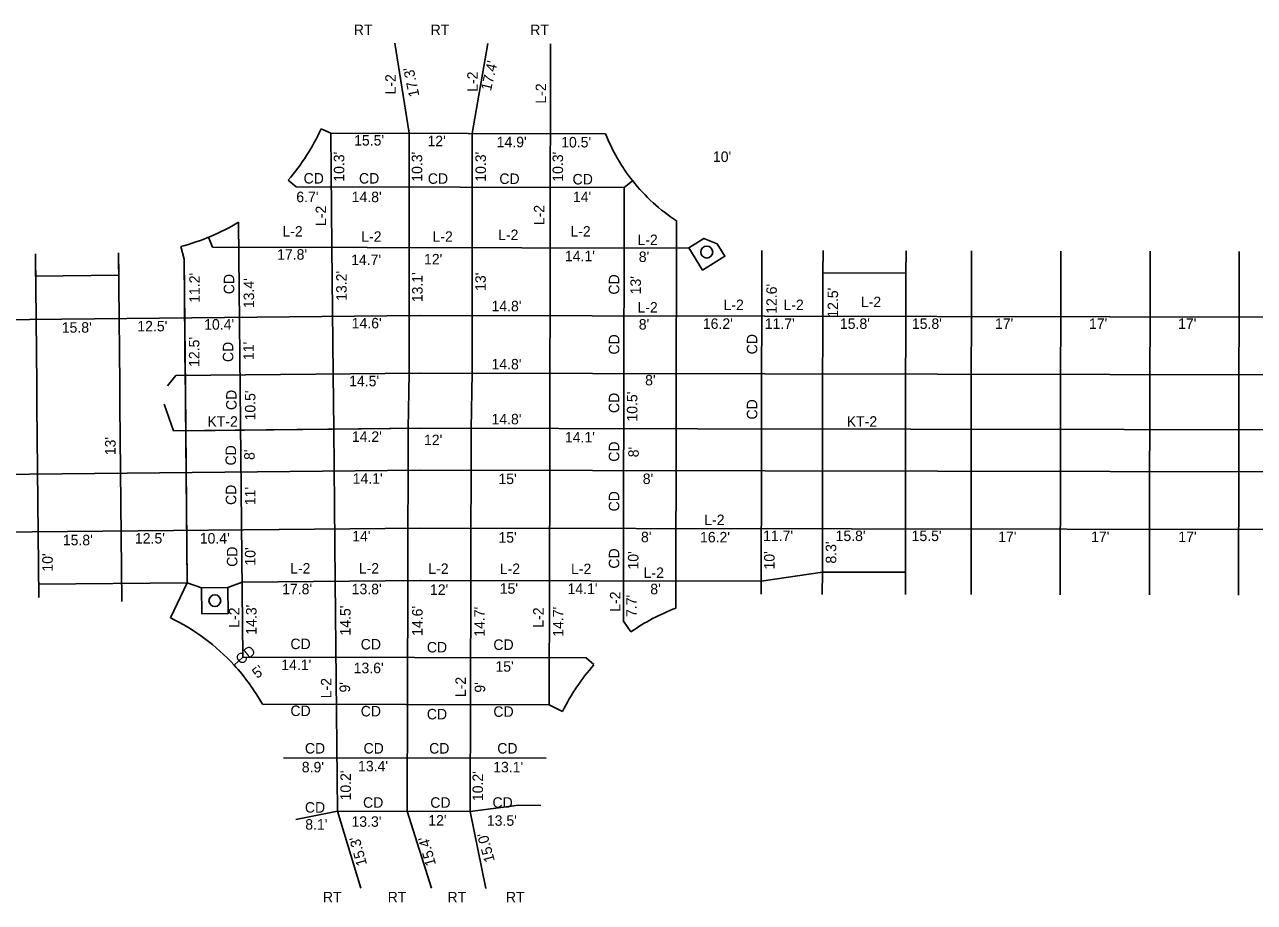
# Model space of a CAD drawing. Extents: x 4995357 to 4999033, y 3881202 to 3881750.
# Drawn here: x 4995617.7 to 4995852.2, y 3881583 to 3881750.3 of the extents above; entities that cross this region are included whole.
import ezdxf

# ---------------------------------------------------------------- set-up
doc = ezdxf.new("R2010")
doc.units = 0
for name, color, linetype in [('dsn3DCenterLine', 7, 'Continuous'), ('dsn3DCurbFormgrade', 7, 'Continuous'), ('dsn3DCurbTop', 7, 'Continuous'), ('dsn3DDitchFront', 7, 'Continuous'), ('dsn3DDNC', 7, 'Continuous'), ('dsn3DExistingPvmtBtm', 7, 'Continuous'), ('dsn3DGroundLineIntercept', 7, 'Continuous'), ('dsn3DIntakeWell', 7, 'Continuous')]:
    doc.layers.add(name, color=color, linetype=linetype)

msp = doc.modelspace()

# ---------------------------------------------------------------- linework, layer by layer
at = {"layer": 'dsn3DCurbFormgrade'}
for p, q in [((4995731.95, 3881673.26), (4995732.03, 3881719.19)), ((4995652.8, 3881709.73), (4995653.56, 3881707.88)), ((4995620.03, 3881681.6), (4995619.78, 3881706.6)), ((4995635.87, 3881681.76), (4995635.62, 3881706.76)), ((4995647.52, 3881708), (4995648.13, 3881705.57)), ((4995676.55, 3881683.66), (4995676.31, 3881707.83)), ((4995691.04, 3881683.81), (4995691.03, 3881707.8)), ((4995703.04, 3881683.81), (4995703.03, 3881707.77)), ((4995717.85, 3881673.28), (4995717.91, 3881707.74)), ((4995758.19, 3881670.71), (4995758.26, 3881707.21)), ((4995769.93, 3881707.19), (4995769.92, 3881702.94)), ((4995798.26, 3881707.14), (4995798.2, 3881670.64)), ((4995815.26, 3881707.11), (4995815.2, 3881670.61)), ((4995832.26, 3881707.07), (4995832.2, 3881670.57)), ((4995849.26, 3881707.04), (4995849.2, 3881670.54)), ((4995648.36, 3881681.88), (4995648.13, 3881705.57)), ((4995648.38, 3881680.71), (4995648.13, 3881705.57)), ((4995769.86, 3881670.69), (4995769.92, 3881702.94)), ((4995785.68, 3881670.66), (4995785.74, 3881702.91)), ((4995676.65, 3881673.17), (4995676.55, 3881683.66)), ((4995690.85, 3881673.31), (4995691.04, 3881683.81)), ((4995702.85, 3881673.31), (4995703.04, 3881683.81)), ((4995648.74, 3881643.89), (4995648.38, 3881680.71)), ((4995620.44, 3881641.1), (4995620.07, 3881677.6)), ((4995636.28, 3881640.35), (4995635.91, 3881677.76)), ((4995648.74, 3881643.89), (4995648.4, 3881677.88)), ((4995690.85, 3881673.31), (4995690.77, 3881644.3)), ((4995702.85, 3881673.31), (4995702.77, 3881644.31)), ((4995717.82, 3881665.28), (4995717.85, 3881673.28)), ((4995731.95, 3881673.26), (4995731.92, 3881665.26)), ((4995676.94, 3881644.17), (4995676.65, 3881673.17)), ((4995758.18, 3881667.72), (4995758.13, 3881641.71)), ((4995769.84, 3881667.7), (4995769.8, 3881645.94)), ((4995785.66, 3881667.67), (4995785.62, 3881645.91)), ((4995798.19, 3881667.64), (4995798.14, 3881641.64)), ((4995815.19, 3881667.61), (4995815.14, 3881641.61)), ((4995832.19, 3881667.57), (4995832.14, 3881641.57)), ((4995849.19, 3881667.54), (4995849.14, 3881641.54)), ((4995717.82, 3881665.28), (4995717.78, 3881644.28)), ((4995731.92, 3881665.26), (4995731.88, 3881644.26)), ((4995645.53, 3881637.22), (4995648.74, 3881643.89)), ((4995659.33, 3881629.72), (4995724.77, 3881629.61)), ((4995663.06, 3881620.74), (4995717.74, 3881620.65)), ((4995702.66, 3881600.33), (4995711.91, 3881601.49)), ((4995711.91, 3881601.49), (4995716.16, 3881601.47)), ((4995669.44, 3881598.79), (4995677.38, 3881600.37)), ((4995677.38, 3881600.37), (4995702.66, 3881600.33)), ((4995677.38, 3881600.37), (4995681.84, 3881585.7)), ((4995690.66, 3881600.35), (4995695.28, 3881585.68))]:
    msp.add_line(p, q, dxfattribs=at)
at = {"layer": 'dsn3DCurbTop'}
for p, q in [((4995620.07, 3881677.6), (4995620.03, 3881681.6)), ((4995635.91, 3881677.76), (4995635.87, 3881681.76)), ((4995758.19, 3881670.71), (4995758.18, 3881667.72)), ((4995769.86, 3881670.69), (4995769.84, 3881667.7)), ((4995785.66, 3881667.67), (4995785.68, 3881670.66)), ((4995798.19, 3881667.64), (4995798.2, 3881670.64)), ((4995815.2, 3881670.61), (4995815.19, 3881667.61)), ((4995832.19, 3881667.57), (4995832.2, 3881670.57)), ((4995849.19, 3881667.54), (4995849.2, 3881670.54)), ((4995733.29, 3881634.53), (4995731.87, 3881636.58))]:
    msp.add_line(p, q, dxfattribs=at)
at = {"layer": 'dsn3DDitchFront'}
for p, q in [((4995644.96, 3881681.4), (4995646.53, 3881683.37)), ((4995644.36, 3881677.95), (4995646.12, 3881672.86)), ((4995646.12, 3881672.86), (4995693.11, 3881673.33)), ((4995693.11, 3881673.33), (4995746.05, 3881673.23)), ((4995657.66, 3881628.2), (4995659.33, 3881629.72))]:
    msp.add_line(p, q, dxfattribs=at)
msp.add_lwpolyline([(4995988.27, 3881680.81), (4995867.93, 3881673.01), (4995746.05, 3881673.23)], dxfattribs=at)
at = {"layer": 'dsn3DDNC'}
for p, q in [((4995691.02, 3881729.55), (4995688.29, 3881746.72)), ((4995703.02, 3881729.52), (4995706.04, 3881746.63)), ((4995717.91, 3881707.74), (4995717.98, 3881746.61)), ((4995676.31, 3881707.83), (4995676.09, 3881729.58)), ((4995691.03, 3881707.8), (4995691.02, 3881729.55)), ((4995703.03, 3881707.77), (4995703.02, 3881729.52)), ((4995653.56, 3881707.88), (4995742, 3881707.69)), ((4995742, 3881707.69), (4995744.33, 3881707.71)), ((4995412.22, 3881692.03), (4995693.02, 3881694.83)), ((4995693.02, 3881694.83), (4996408.86, 3881693.52)), ((4995646.53, 3881683.37), (4995693.13, 3881683.83)), ((4995693.07, 3881683.83), (4996408.76, 3881682.52)), ((4995648.45, 3881672.88), (4995693.11, 3881673.33)), ((4995693.11, 3881673.33), (4995746.05, 3881673.23)), ((4995360.43, 3881662.01), (4995693.14, 3881665.33)), ((4995693.14, 3881665.33), (4996010.6, 3881664.75)), ((4995360.54, 3881651.01), (4995693.19, 3881654.33)), ((4995693.19, 3881654.33), (4996010.8, 3881653.75)), ((4995769.8, 3881645.94), (4995758.13, 3881644.21)), ((4995620.41, 3881643.6), (4995648.74, 3881643.89)), ((4995648.74, 3881643.89), (4995651.47, 3881642.96)), ((4995656.47, 3881643.01), (4995659.18, 3881643.99)), ((4995659.18, 3881643.99), (4995693.29, 3881644.33)), ((4995677.38, 3881600.37), (4995676.94, 3881644.17)), ((4995690.77, 3881644.3), (4995690.66, 3881600.35)), ((4995693.17, 3881644.33), (4995758.13, 3881644.21)), ((4995702.77, 3881644.31), (4995702.66, 3881600.33)), ((4995717.78, 3881644.28), (4995717.74, 3881620.65)), ((4995731.88, 3881644.26), (4995731.87, 3881636.58)), ((4995702.66, 3881600.33), (4995705.62, 3881585.66))]:
    msp.add_line(p, q, dxfattribs=at)
at = {"layer": 'dsn3DExistingPvmtBtm'}
for p, q in [((4995619.78, 3881706.6), (4995619.83, 3881702.35)), ((4995635.66, 3881702.51), (4995635.62, 3881706.76)), ((4995785.75, 3881707.16), (4995785.74, 3881702.91)), ((4995619.83, 3881702.35), (4995635.66, 3881702.51)), ((4995785.74, 3881702.91), (4995769.92, 3881702.94))]:
    msp.add_line(p, q, dxfattribs=at)
for points in [[(4995744.33, 3881707.71), (4995747.21, 3881709.51), (4995748.46, 3881708.99), (4995749.72, 3881708.51), (4995751.22, 3881706.11), (4995746.97, 3881703.47)], [(4995651.47, 3881642.96), (4995656.47, 3881643.01), (4995656.52, 3881638.01), (4995651.52, 3881637.96)]]:
    msp.add_lwpolyline(points, close=True, dxfattribs=at)
msp.add_lwpolyline([(4995769.79, 3881641.69), (4995769.8, 3881645.94), (4995785.62, 3881645.91), (4995785.63, 3881641.66)], dxfattribs=at)
for centre, radius in [((4995747.77, 3881706.91), 1.13), ((4995653.99, 3881640.48), 1.12)]:
    msp.add_circle(centre, radius, dxfattribs=at)
at = {"layer": 'dsn3DGroundLineIntercept'}
for p, q in [((4995674.23, 3881730.42), (4995676.09, 3881729.58)), ((4995676.09, 3881729.58), (4995728.48, 3881729.47)), ((4995668, 3881720.63), (4995669.51, 3881719.32)), ((4995733.64, 3881720.47), (4995732.03, 3881719.19)), ((4995669.51, 3881719.32), (4995732.03, 3881719.19)), ((4995659.33, 3881629.72), (4995658.5, 3881712.6)), ((4995741.87, 3881639.07), (4995742.01, 3881712.85))]:
    msp.add_line(p, q, dxfattribs=at)
at = {"layer": 'dsn3DIntakeWell'}
for p, q in [((4995742.01, 3881712.85), (4995741.87, 3881639.07)), ((4995726.26, 3881628.29), (4995724.77, 3881629.61)), ((4995720.28, 3881619.39), (4995717.74, 3881620.65)), ((4995667.06, 3881610.56), (4995717.14, 3881610.48))]:
    msp.add_line(p, q, dxfattribs=at)
for points in [[(4995674.23, 3881730.42), (4995676.09, 3881729.58), (4995728.48, 3881729.47)], [(4995733.64, 3881720.47), (4995732.03, 3881719.19), (4995669.51, 3881719.32), (4995668, 3881720.63)], [(4995733.29, 3881634.53), (4995731.87, 3881636.58), (4995731.92, 3881665.26), (4995731.95, 3881673.26), (4995732.03, 3881719.19), (4995733.64, 3881720.47)], [(4995658.5, 3881712.6), (4995659.33, 3881629.72), (4995657.66, 3881628.2)], [(4995645.53, 3881637.22), (4995648.74, 3881643.89), (4995648.13, 3881705.57), (4995647.52, 3881708)], [(4995657.66, 3881628.2), (4995659.33, 3881629.72), (4995724.77, 3881629.61), (4995726.26, 3881628.29)], [(4995720.28, 3881619.39), (4995717.74, 3881620.65), (4995663.06, 3881620.74)]]:
    msp.add_lwpolyline(points, dxfattribs=at)
for centre, radius, start, end in [((4995637.73, 3881746.78), 40, 319.1764, 335.8497), ((4995761.08, 3881742.2), 35, 201.342, 218.3935), ((4995761.08, 3881742.2), 35, 218.3935, 236.9925), ((4995637.73, 3881746.78), 40, 284.1655, 301.2838), ((4995756.16, 3881601.71), 40, 110.9307, 124.8702), ((4995628.17, 3881601.18), 40, 42.501, 64.2814), ((4995628.17, 3881601.18), 40, 29.2748, 42.501), ((4995756.16, 3881601.71), 40, 138.3718, 153.7724)]:
    msp.add_arc(centre, radius, start, end, dxfattribs=at)

# ---------------------------------------------------------------- texts
at = {"layer": 'dsn3DCenterLine'}
for s, p in [('RT', (4995680.48, 3881748.26)), ('RT', (4995695.13, 3881748.26)), ('RT', (4995714.11, 3881748.26)), ("15.5'", (4995680.54, 3881727.21)), ("12'", (4995694.53, 3881727.08)), ("14.9'", (4995707.72, 3881726.89)), ("10.5'", (4995720.01, 3881726.85)), ("10'", (4995748.94, 3881724.09)), ('CD', (4995670.91, 3881719.97)), ('CD', (4995681.47, 3881719.97)), ('CD', (4995694.59, 3881719.92)), ('CD', (4995708.23, 3881719.89)), ('CD', (4995722.19, 3881719.8)), ("6.7'", (4995669.52, 3881716.43)), ("14.8'", (4995680.08, 3881716.43)), ("14'", (4995722.25, 3881716.43)), ('L-2', (4995666.87, 3881709.86)), ('L-2', (4995681.9, 3881708.87)), ('L-2', (4995695.48, 3881708.87)), ('L-2', (4995708, 3881709.2)), ('L-2', (4995721.77, 3881709.86)), ('L-2', (4995734.55, 3881708.25)), ("17.8'", (4995665.86, 3881705.46)), ("14.7'", (4995679.97, 3881704.43)), ("12'", (4995693.87, 3881704.56)), ("14.1'", (4995720.73, 3881705.16)), ("8'", (4995734.81, 3881705.02)), ("14.8'", (4995706.73, 3881695.63)), ('L-2', (4995734.55, 3881695.38)), ('L-2', (4995750.96, 3881695.86)), ('L-2', (4995762.39, 3881695.86)), ('L-2', (4995777.14, 3881696.42)), ("14.6'", (4995680.08, 3881692.37)), ("15.8'", (4995624.81, 3881691.55)), ("12.5'", (4995639.22, 3881691.8)), ("10.4'", (4995651.95, 3881692.13)), ("8'", (4995734.81, 3881692.14)), ("16.2'", (4995747.02, 3881692.27)), ("11.7'", (4995758.82, 3881692.27)), ("15.8'", (4995773.15, 3881692.27)), ("15.8'", (4995786.87, 3881692.27)), ("17'", (4995802.71, 3881692.27)), ("17'", (4995820.63, 3881692.27)), ("17'", (4995837.61, 3881692.27)), ("14.8'", (4995706.73, 3881684.55)), ("14.5'", (4995679.59, 3881681.34)), ("8'", (4995736.02, 3881681.51)), ('KT-2', (4995652.58, 3881673.63)), ("14.8'", (4995706.73, 3881674.08)), ('KT-2', (4995774.46, 3881673.63)), ("14.2'", (4995680.11, 3881670.75)), ("12'", (4995693.87, 3881670.12)), ("14.1'", (4995720.73, 3881670.63)), ("14.1'", (4995680.27, 3881662.77)), ("15'", (4995708.05, 3881662.7)), ("8'", (4995735.57, 3881662.71)), ("15.8'", (4995625.01, 3881651.04)), ("12.5'", (4995638.76, 3881651.37)), ("10.4'", (4995651.12, 3881651.37)), ("14'", (4995680.19, 3881651.79)), ("15'", (4995708.05, 3881651.54)), ("8'", (4995735.23, 3881651.63)), ("16.2'", (4995746.48, 3881651.59)), ("11.7'", (4995758.5, 3881651.84)), ("15.8'", (4995772.33, 3881651.84)), ("15.5'", (4995786.82, 3881651.84)), ("17'", (4995803.32, 3881651.66)), ("17'", (4995821.03, 3881651.66)), ("17'", (4995837.67, 3881651.66)), ('L-2', (4995668.34, 3881645.65)), ('L-2', (4995681.43, 3881645.65)), ('L-2', (4995694.69, 3881645.58)), ('L-2', (4995708.31, 3881645.56)), ('L-2', (4995721.89, 3881645.54)), ('L-2', (4995735.73, 3881644.81)), ("17.8'", (4995666.82, 3881641.71)), ("13.8'", (4995680.08, 3881641.71)), ("12'", (4995695, 3881641.59)), ("15'", (4995708.3, 3881641.8)), ("14.1'", (4995721.23, 3881641.76)), ("8'", (4995737, 3881641.71)), ('CD', (4995668.4, 3881631.25)), ('CD', (4995681.8, 3881631.18)), ('CD', (4995694.41, 3881630.61)), ('CD', (4995707.09, 3881631.1)), ("14.1'", (4995666.66, 3881627.26)), ("13.6'", (4995680.46, 3881626.66)), ("15'", (4995707.48, 3881626.95)), ('CD', (4995668.4, 3881618.5)), ('CD', (4995681.8, 3881618.43)), ('CD', (4995694.41, 3881617.86)), ('CD', (4995707.09, 3881618.35)), ('CD', (4995671.16, 3881611.35)), ('CD', (4995682.34, 3881611.35)), ('CD', (4995694.84, 3881611.35)), ('CD', (4995707.83, 3881611.35)), ("13.4'", (4995681.29, 3881607.96)), ("8.9'", (4995670.57, 3881607.77)), ("13.1'", (4995707.05, 3881607.77)), ('CD', (4995682.24, 3881601.02)), ('CD', (4995695.06, 3881601.02)), ('CD', (4995706.92, 3881601.02)), ('CD', (4995671.16, 3881600.09)), ("8.1'", (4995671.23, 3881596.85)), ("13.3'", (4995680.04, 3881597.39)), ("12'", (4995694.68, 3881597.63)), ("13.5'", (4995705.85, 3881597.58)), ('RT', (4995674.59, 3881582.99)), ('RT', (4995686.94, 3881582.99)), ('RT', (4995698.34, 3881582.99)), ('RT', (4995709.48, 3881582.99))]:
    msp.add_text(s, height=2, dxfattribs=at).set_placement(p)
for s, rotation, p in [("17.3'", 101.8548, (4995693, 3881736.7)), ("17.4'", 76.8907, (4995706.62, 3881737.52)), ('L-2', 90, (4995688.48, 3881736.95)), ('L-2', 90, (4995704.1, 3881737.45)), ('L-2', 90, (4995717.15, 3881735.2)), ("10.3'", 90, (4995678.67, 3881720.32)), ("10.3'", 90, (4995693.53, 3881720.32)), ("10.3'", 90, (4995705.67, 3881720.32)), ("10.3'", 90, (4995720.37, 3881720.32)), ('L-2', 90, (4995675.2, 3881711.88)), ('L-2', 90, (4995716.81, 3881712.04)), ("11.2'", 90, (4995651.12, 3881697.25)), ('CD', 90, (4995657.69, 3881698.88)), ("13.4'", 90, (4995661.47, 3881696.23)), ("13.2'", 90, (4995679.12, 3881697.61)), ("13.1'", 90, (4995693.6, 3881697.36)), ("13'", 90, (4995705.64, 3881699.51)), ('CD', 90, (4995731.09, 3881698.81)), ("13'", 90, (4995735.21, 3881698.86)), ("12.6'", 90, (4995761.12, 3881695.15)), ("12.5'", 90, (4995772.8, 3881694.41)), ("12.5'", 90, (4995651.05, 3881685.03)), ('CD', 90, (4995657.51, 3881685.95)), ("11'", 90, (4995661.41, 3881686.34)), ('CD', 90, (4995731.09, 3881687.38)), ('CD', 90, (4995757.4, 3881687.43)), ('CD', 90, (4995658.14, 3881676.81)), ("10.5'", 90, (4995661.73, 3881674.83)), ('CD', 90, (4995731.09, 3881676.24)), ("10.5'", 90, (4995734.54, 3881674.61)), ('CD', 90, (4995757.4, 3881675.01)), ("13'", 90, (4995635.07, 3881668.2)), ('CD', 90, (4995658.03, 3881666.25)), ("8'", 90, (4995661.58, 3881667.3)), ('CD', 90, (4995731.09, 3881666.96)), ("8'", 90, (4995734.8, 3881667.8)), ('CD', 90, (4995658.07, 3881658.72)), ("11'", 90, (4995661.72, 3881658.68)), ('CD', 90, (4995731.09, 3881657.49)), ('L-2', 359.8949, (4995747.29, 3881654.89)), ('CD', 90, (4995658.29, 3881646.94)), ("10'", 90, (4995661.73, 3881647.17)), ('CD', 90, (4995731.09, 3881646.59)), ("8.3'", 90, (4995772.45, 3881647.55)), ("10'", 90, (4995623.09, 3881646.02)), ("10'", 90, (4995734.74, 3881646.42)), ("10'", 90, (4995760.69, 3881646.42)), ('L-2', 90, (4995731.31, 3881638.37)), ("7.7'", 90, (4995734.41, 3881637.38)), ('L-2', 90, (4995658.67, 3881635.33)), ("14.3'", 90, (4995661.94, 3881634)), ("14.5'", 90, (4995679.87, 3881633.83)), ("14.6'", 90, (4995693.6, 3881633.77)), ("14.7'", 90, (4995705.45, 3881633.61)), ('L-2', 90, (4995716.67, 3881635.33)), ("14.7'", 90, (4995720.44, 3881633.61)), ('CD', 38.5155, (4995658.95, 3881628.16)), ("5'", 38.5155, (4995662.08, 3881625.55)), ('L-2', 90, (4995676.21, 3881621.88)), ("9'", 90, (4995679.77, 3881622.98)), ('L-2', 90, (4995701.86, 3881622.1)), ("9'", 90, (4995705.52, 3881622.96)), ("10.2'", 90, (4995679.92, 3881602.41)), ("10.2'", 90, (4995705.11, 3881602.29)), ("15.0'", 105.4949, (4995707.39, 3881590.93)), ("15.3'", 105.4949, (4995683.03, 3881590.21)), ("15.4'", 105.4949, (4995696.17, 3881590.21))]:
    msp.add_text(s, height=2, rotation=rotation, dxfattribs=at).set_placement(p)

doc.saveas('drawing.dxf')
